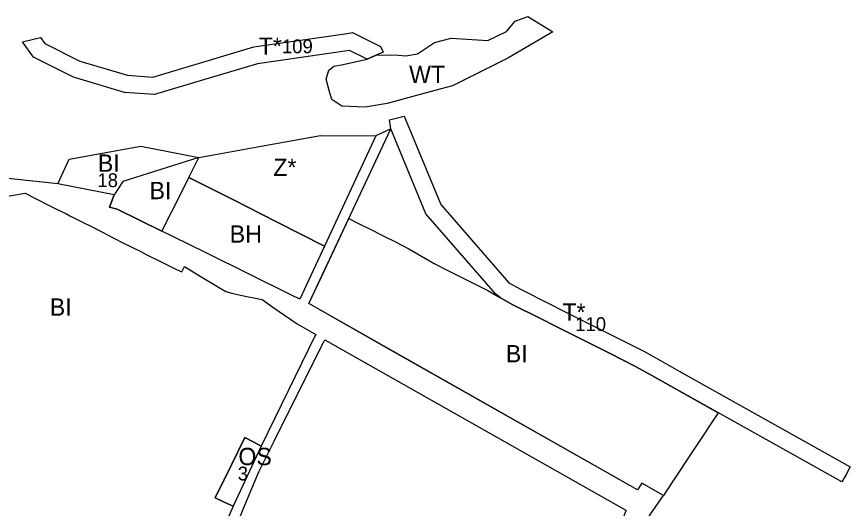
# Model space of a CAD drawing. Extents: x -521621 to -516769, y -1190068 to -1185078.
# Drawn here: x -518605.8 to -518124.1, y -1187040.9 to -1186756.7 of the extents above; entities that cross this region are included whole.
import ezdxf

# ---------------------------------------------------------------- set-up
doc = ezdxf.new("R2010")
doc.units = 0
for name, color, linetype in [('bydleni_n', 7, 'Continuous'), ('bydleni_s', 7, 'Continuous'), ('fpl_id', 7, 'Continuous'), ('s_zelen_s', 7, 'Continuous'), ('v_infrastr_n', 7, 'Continuous'), ('v_infrastr_s', 7, 'Continuous'), ('voda_s', 7, 'Continuous')]:
    doc.layers.add(name, color=color, linetype=linetype)

msp = doc.modelspace()

# ---------------------------------------------------------------- linework, layer by layer
at = {"layer": 'bydleni_n'}
msp.add_lwpolyline([(-518582.03, -1186853.35), (-518575.51, -1186839.1), (-518534.01, -1186831.46), (-518500.52, -1186838.13), (-518544.49, -1186852.05), (-518549.49, -1186859.73)], close=True, dxfattribs=at)
at = {"layer": 'bydleni_s'}
for points in [[(-518521.93, -1186880.66), (-518510.46, -1186857.88), (-518506.31, -1186849.63), (-518500.52, -1186838.13), (-518544.49, -1186852.05), (-518549.49, -1186859.73), (-518552.08, -1186866.83), (-518547.66, -1186867.89), (-518521.93, -1186880.66)], [(-518521.93, -1186880.66), (-518510.46, -1186857.88), (-518506.31, -1186849.63)], [(-518506.31, -1186849.63), (-518480.56, -1186862.66)], [(-518627.41, -1186873.54), (-518623.03, -1186862.59), (-518603.14, -1186859.16)], [(-518603.14, -1186859.16), (-518600.85, -1186858.76), (-518587.77, -1186865.41)], [(-518480.56, -1186862.66), (-518455.58, -1186875.31)], [(-518587.77, -1186865.41), (-518582.71, -1186867.92), (-518577.42, -1186870.55), (-518575.07, -1186871.74), (-518573.14, -1186872.72), (-518568.51, -1186875.07), (-518566.67, -1186876), (-518563.77, -1186877.47), (-518555.76, -1186881.53), (-518553.73, -1186882.56), (-518544.88, -1186887.16), (-518534.07, -1186892.52), (-518530.93, -1186894.08), (-518522.26, -1186898.38), (-518513.38, -1186902.79), (-518510.39, -1186904.27), (-518508.85, -1186901.18)], [(-518455.58, -1186875.31), (-518428.01, -1186889.26), (-518442.24, -1186920.02), (-518447.29, -1186917.52)], [(-518515.56, -1186883.8), (-518521.93, -1186880.66)], [(-518496.37, -1186893.28), (-518515.56, -1186883.8)], [(-518471.11, -1186905.76), (-518496.37, -1186893.28)], [(-518508.85, -1186901.18), (-518499.77, -1186906.66)], [(-518499.77, -1186906.66), (-518491.09, -1186911.91), (-518484.96, -1186915.61), (-518481.38, -1186916.55)], [(-518447.29, -1186917.52), (-518471.11, -1186905.76)], [(-518481.38, -1186916.55), (-518478.26, -1186917.38), (-518472.84, -1186918.44), (-518468.71, -1186919.24)], [(-518468.71, -1186919.24), (-518463.96, -1186920.17), (-518457.7, -1186924.55)], [(-518457.7, -1186924.55), (-518447.35, -1186931.79), (-518443.81, -1186934.27), (-518432.99, -1186940.4), (-518433.57, -1186941.43), (-518464.51, -1187005.06), (-518469.1, -1187002.53), (-518473.89, -1186999.89), (-518481.7, -1187015.82), (-518491.05, -1187034.9)], [(-518465.82, -1187019.86), (-518456.99, -1187002.02), (-518440.92, -1186969.52), (-518428.52, -1186944.97), (-518427.64, -1186943.43), (-518253.7, -1187041.94), (-518253.88, -1187042.41), (-518258.22, -1187053.89), (-518258.57, -1187054.82), (-518278.8, -1187088.37), (-518293.65, -1187112.46), (-518297.8, -1187123.36), (-518300.17, -1187129.58), (-518312.46, -1187155.36), (-518314.28, -1187159.18), (-518325.47, -1187154.57)], [(-518433.57, -1187110.12), (-518441.83, -1187106.71), (-518450.69, -1187103.04), (-518459.83, -1187099.26), (-518468.13, -1187095.83), (-518476.44, -1187092.39), (-518487.49, -1187087.82), (-518488.23, -1187089.2), (-518493.04, -1187087.16), (-518474.86, -1187041.46), (-518465.82, -1187019.86)], [(-518491.05, -1187034.9), (-518485.93, -1187037.37), (-518480.71, -1187039.72), (-518489.07, -1187058.7)]]:
    msp.add_lwpolyline(points, dxfattribs=at)
msp.add_lwpolyline([(-518408.98, -1186875.78), (-518401.24, -1186879.69), (-518394.12, -1186883.3), (-518386.57, -1186887.11), (-518379.12, -1186890.88), (-518364.49, -1186899.38), (-518356.21, -1186903.58), (-518333.61, -1186915.03), (-518326.21, -1186919.18), (-518319.05, -1186923.2), (-518302.73, -1186931.42), (-518294.42, -1186935.61), (-518271.38, -1186947.21), (-518263.64, -1186951.11), (-518248.17, -1186958.9), (-518238.68, -1186964.21), (-518227.87, -1186970.26), (-518200.37, -1186985.64), (-518227.43, -1187026.44), (-518232, -1187033.55), (-518244.57, -1187026.43), (-518247.09, -1187030.18), (-518437.07, -1186922.57), (-518437, -1186922.44), (-518429.54, -1186906.66), (-518413.79, -1186873.35)], close=True, dxfattribs=at)
at = {"layer": 's_zelen_s'}
for points in [[(-518464.52, -1186831.6), (-518430.15, -1186825.45)], [(-518430.15, -1186825.45), (-518398.17, -1186825.64), (-518428.01, -1186889.26), (-518455.58, -1186875.31)], [(-518480.56, -1186862.66), (-518506.31, -1186849.63), (-518500.52, -1186838.13), (-518464.52, -1186831.6)], [(-518455.58, -1186875.31), (-518480.56, -1186862.66)]]:
    msp.add_lwpolyline(points, dxfattribs=at)
at = {"layer": 'v_infrastr_n'}
for points in [[(-518589.47, -1186772.24), (-518569.32, -1186782.32), (-518541.73, -1186790.55), (-518527.2, -1186791.58), (-518509.83, -1186786.39), (-518468.84, -1186774.15), (-518414.86, -1186766.32), (-518411.76, -1186765.87), (-518395.6, -1186773.95), (-518394.12, -1186777.23), (-518397.68, -1186778.82), (-518403.25, -1186781.31), (-518413.43, -1186776.22), (-518466.68, -1186783.94), (-518499.74, -1186793.81), (-518526.09, -1186801.68), (-518543.53, -1186800.45), (-518573.01, -1186791.65), (-518596.15, -1186780.08), (-518602.48, -1186771.28), (-518592.03, -1186768.69)], [(-518369.34, -1186870.58), (-518389.67, -1186821.59), (-518390.39, -1186816.31), (-518381.92, -1186814.18), (-518360.74, -1186865.22), (-518321.32, -1186910.46), (-518314.35, -1186914.37), (-518298.23, -1186922.49), (-518289.92, -1186926.67), (-518266.88, -1186938.28), (-518259.14, -1186942.18), (-518243.48, -1186950.07), (-518233.8, -1186955.48), (-518222.99, -1186961.53), (-518124.07, -1187016.86), (-518126.55, -1187021.3), (-518128.95, -1187025.59), (-518227.87, -1186970.26), (-518238.68, -1186964.21), (-518248.17, -1186958.9), (-518263.64, -1186951.11), (-518271.38, -1186947.21), (-518294.42, -1186935.61), (-518302.73, -1186931.42), (-518319.05, -1186923.2), (-518326.21, -1186919.18), (-518328.85, -1186917.03)], [(-518481.7, -1187015.82), (-518473.89, -1186999.89), (-518469.1, -1187002.53), (-518464.51, -1187005.06), (-518480.71, -1187039.72), (-518485.93, -1187037.37), (-518491.05, -1187034.9)]]:
    msp.add_lwpolyline(points, close=True, dxfattribs=at)
at = {"layer": 'v_infrastr_s'}
for points in [[(-518437, -1186922.44), (-518412.82, -1186871.29), (-518389.67, -1186821.59), (-518398.17, -1186825.64), (-518428.01, -1186889.26), (-518442.24, -1186920.02)], [(-518442.24, -1186920.02), (-518447.29, -1186917.52), (-518471.11, -1186905.76), (-518496.37, -1186893.28), (-518515.56, -1186883.8), (-518521.93, -1186880.66), (-518547.66, -1186867.89), (-518552.08, -1186866.83), (-518549.49, -1186859.73), (-518582.03, -1186853.35), (-518607.21, -1186850.56), (-518632.89, -1186847.81)], [(-518653.4, -1186888.53), (-518648.08, -1186891.27), (-518643.96, -1186881.69), (-518638.7, -1186883.84), (-518633.03, -1186870.95), (-518627.41, -1186873.54), (-518623.03, -1186862.59), (-518603.14, -1186859.16), (-518600.85, -1186858.76), (-518587.77, -1186865.41)], [(-518587.77, -1186865.41), (-518582.71, -1186867.92), (-518577.42, -1186870.55), (-518575.07, -1186871.74), (-518573.14, -1186872.72), (-518568.51, -1186875.07), (-518566.67, -1186876), (-518563.77, -1186877.47), (-518555.76, -1186881.53), (-518553.73, -1186882.56), (-518544.88, -1186887.16), (-518534.07, -1186892.52), (-518530.93, -1186894.08), (-518522.26, -1186898.38), (-518513.38, -1186902.79), (-518510.39, -1186904.27), (-518508.85, -1186901.18)], [(-518508.85, -1186901.18), (-518499.77, -1186906.66), (-518491.09, -1186911.91), (-518484.96, -1186915.61), (-518481.38, -1186916.55), (-518478.26, -1186917.38), (-518472.84, -1186918.44), (-518468.71, -1186919.24), (-518463.96, -1186920.17), (-518457.7, -1186924.55), (-518447.35, -1186931.79), (-518443.81, -1186934.27)], [(-518437.07, -1186922.57), (-518437, -1186922.44)], [(-518390.3, -1186949.06), (-518437.07, -1186922.57)], [(-518443.81, -1186934.27), (-518432.99, -1186940.4), (-518433.57, -1186941.43)], [(-518433.57, -1186941.43), (-518464.51, -1187005.06), (-518480.71, -1187039.72), (-518489.07, -1187058.7), (-518498.38, -1187083.17)], [(-518493.04, -1187087.16), (-518474.86, -1187041.46), (-518465.82, -1187019.86), (-518456.99, -1187002.02), (-518440.92, -1186969.52), (-518428.52, -1186944.97)], [(-518428.52, -1186944.97), (-518427.64, -1186943.43), (-518253.7, -1187041.94), (-518253.88, -1187042.41), (-518253.88, -1187042.41), (-518258.22, -1187053.89)], [(-518248.17, -1187058.62), (-518239.49, -1187044.29), (-518232, -1187033.55), (-518244.57, -1187026.43), (-518247.09, -1187030.18), (-518390.3, -1186949.06)]]:
    msp.add_lwpolyline(points, dxfattribs=at)
at = {"layer": 'voda_s'}
for points in [[(-518403.25, -1186781.31), (-518397.68, -1186778.82), (-518394.24, -1186778.87), (-518389.23, -1186778.81), (-518385.34, -1186779.01), (-518380.85, -1186779.29), (-518374.21, -1186778.15), (-518364.39, -1186771.69), (-518354.7, -1186769.11), (-518333.48, -1186770.37), (-518322.73, -1186765.23), (-518317.72, -1186759.23), (-518310.33, -1186756.68), (-518295.99, -1186765.5), (-518322.07, -1186780.62), (-518354.02, -1186796.67), (-518364.14, -1186799.41), (-518364.14, -1186799.41), (-518391.67, -1186806.93)], [(-518418.05, -1186784.46), (-518403.25, -1186781.31)], [(-518425.14, -1186799.35), (-518426.98, -1186792.77), (-518425.37, -1186787.56), (-518422.54, -1186785.22), (-518418.05, -1186784.46)], [(-518423.69, -1186804.53), (-518425.14, -1186799.35)], [(-518391.67, -1186806.93), (-518404.47, -1186809.04), (-518417.97, -1186808.33), (-518423.69, -1186804.53)]]:
    msp.add_lwpolyline(points, dxfattribs=at)

# ---------------------------------------------------------------- texts
at = {"layer": 'bydleni_n'}
msp.add_text('BI', height=10, dxfattribs=at).set_placement((-518558.9, -1186846.35))
at = {"layer": 'bydleni_s'}
for s, p in [('BI', (-518529.01, -1186862.19)), ('BH', (-518482.67, -1186887.34)), ('BI', (-518586.67, -1186929.54)), ('BI', (-518323.15, -1186956.51))]:
    msp.add_text(s, height=10, dxfattribs=at).set_placement(p)
at = {"layer": 'fpl_id'}
for s, p in [('109', (-518452.52, -1186777.84)), ('18', (-518559.16, -1186855.23)), ('110', (-518283.07, -1186938.4)), ('3', (-518478.06, -1187024.8))]:
    msp.add_text(s, height=8, dxfattribs=at).set_placement(p)
at = {"layer": 's_zelen_s'}
msp.add_text('Z*', height=10, dxfattribs=at).set_placement((-518457.52, -1186848.76))
at = {"layer": 'v_infrastr_n'}
for s, p in [('T*', (-518465.95, -1186778.73)), ('T*', (-518290.47, -1186932.49)), ('OS', (-518477.69, -1187015.94))]:
    msp.add_text(s, height=10, dxfattribs=at).set_placement(p)
at = {"layer": 'voda_s'}
msp.add_text('WT', height=10, dxfattribs=at).set_placement((-518379.04, -1186795.07))

doc.saveas('drawing.dxf')
